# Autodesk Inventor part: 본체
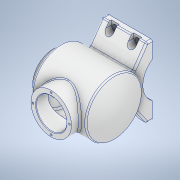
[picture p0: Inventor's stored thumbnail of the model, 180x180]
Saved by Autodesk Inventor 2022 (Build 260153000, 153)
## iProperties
Created: 2023-04
Part Number: 본체
Material: 알루미늄 6061
Document SubType Name: Modeling
Designer: Admin
Density: 2.7 g/cm^3
Appearance: 알루미늄 - 평지
Mass: 1326.81 g
Surface Area: 1066.21 cm^2
Volume: 491.413 cm^3
Author: Admin
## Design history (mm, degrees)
sketch "스케치1" dims "d7" = 226
  geometry: L1 (-211.2, 0)-(105.2, 0) reference; L2 (0, -158.2)-(0, 158.2) reference; L3 (-60, 0)-(-48, 0); L4 (-48, 0)-(-48, 36); L5 (-48, 36)-(-60, 36); L6 (-60, 36)-(-60, 0); L7 (-48, 0)-(60, 0); L8 (60, 0)-(60, 50); L9 (48.336, 50)-(-48, 50); L10 (-48, 50)-(-48, 0); L11 (-34.38, 0)-(50.398, 0); 5 further points
  constraints: 18 end point, 4 parallel, 4 point on line, 2 horizontal, 2 perpendicular, 1 vertical, 4 other
  dimensions: "d0" = 72 diameter of L5 L1; "d1" = 100 diameter of L9 L1; "d3" = 120 distance between parallel lines of L8 L6; "d4" = 108 distance between parallel lines of L8 L4
revolve "회전1" sketch "스케치1" stored, may be unused: angle "d5" = 360 deg
sketch "스케치3" dims "d12" = 226
  geometry: L1 (-60, 0)-(-41, 0); L2 (-41, 0)-(-41, 27); L3 (-41, 27)-(-60, 27); L4 (-60, 27)-(-60, 0); L5 (-41, 0)-(53, 0); L6 (53, 0)-(53, 43); L7 (53, 43)-(-41, 43); L8 (-41, 43)-(-41, 0); L9 (0, -158.2)-(0, 158.2) reference; L10 (-211.2, 0)-(105.2, 0) reference; L11 (48.336, -50)-(48.336, 50) reference; L12 (-60, -36)-(-60, 36) reference; C1 r 106 at (-53, 0); 4 further points
  constraints: 16 end point, 4 parallel, 2 collinear, 2 horizontal, 2 perpendicular, 1 centre point, 1 midpoint, 1 tangent, 3 other
  dimensions: "d8" = 19 distance between parallel lines of L2 L4; "d9" = 54 diameter of L3 L10; "d10" = 86 diameter of L7 L10; "d17" = 7 dimension on C1
revolve "회전2" sketch "스케치3" stored, may be unused: angle "d18" = 90 deg
node "작업 평면1"
sketch "스케치4"
  geometry: L1 (-79.6, 0)-(57.6, 0) reference; L2 (0, -50.4)-(0, 50.4) reference; L3 (-60, -36)-(-60, 36) reference; C1 r 36 at (2, 0); 1 further point
  constraints: 1 centre point, 1 point on line
  dimensions: "d20" = 62 distance from line of C1.centre L3; "d21" = 72 diameter of C1
extrude "돌출1" join sketch "스케치4" stored distance "d22" = 10; taper "d23" = 0 deg
sketch "스케치5"
  geometry: C1 r 36 at (0, 0) reference; C2 r 27 at (0, 0); 1 further point
  constraints: 1 centre point, 1 coincident
  dimensions: "d24" = 54 diameter of C2
extrude "돌출2" cut sketch "스케치5" stored distance "d25" = 10; taper "d26" = 0 deg
sketch "스케치6"
  geometry: L1 (0, -70)-(0, 70) reference; L2 (-70, 0)-(70, 0) reference; A1 r 32.5 centre (0, 0) between (32.5, 0) and (0, -32.5); 3 further points
  constraints: 4 point on circle, 4 point on line, 1 centre point, 1 coincident
  dimensions: "d27" = 65 diameter of A1
hole "구멍1" sketch "스케치6" at (32.5, 0), (0, -32.5), (-32.5, 0), (0, 32.5) diameter "d28" = 3.242; stored, may be unused: countersink angle "d32" = 90 deg, drill point angle "d34" = 118 deg; dims "d29" = 8, "d30" = 4, "d31" = 2, "d33" = 10
sketch "스케치7" dims "d35" = 65
  geometry: L1 (-86, 0)-(82, 0) reference; C1 r 27 at (0, 0) reference; 6 further points
  constraints: 1 coincident, 1 horizontal alignment, 1 point on line, 7 other
  dimensions: "d38" = 360 deg dimension on C1.centre point (-32.5, 0) (derived)
hole "구멍2" sketch "스케치7" at (-32.5, 0), (0, -32.5), (32.5, 0), (0, 32.5) diameter "d40" = 3.242; stored, may be unused: countersink angle "d44" = 90 deg, drill point angle "d46" = 118 deg; dims "d41" = 8, "d42" = 4, "d43" = 2, "d45" = 10
node "작업 평면2"
sketch "스케치8"
  geometry: L1 (0, -70)-(0, 70) reference; L2 (-77, 64.015)-(-77, -74.706); L3 (-77, -62)-(-67, -62); L4 (-67, -62)-(-40.123, -23.615); L5 (-105.4, 0)-(93.4, 0) reference; L6 (-46.557, 0)-(-77, 0); L7 (-77, -62)-(-77, 0); C1 r 43 at (0, 0) reference; A1 r 46.557 centre (0, 0) between (-40.123, -23.615) and (-46.557, 0); 1 further point
  constraints: 10 end point, 4 point on line, 2 point on circle, 1 centre point, 1 coincident, 1 collinear, 1 horizontal, 1 vertical
  dimensions: "d48" = 77 distance between parallel lines of L1 L2; "d49" = 10 distance of L3.start L3.end; "d50" = 55 deg angle of L3 L4; "d51" = 62 distance between parallel lines of L5 L3; "d55" = 93.11303 diameter of A1
extrude "돌출3" join sketch "스케치8" distance "d56" = 80; taper "d57" = 0 deg
sketch "스케치9"
  geometry: L1 (-60, -38.5)-(-108.227, -38.5); L2 (-60, 38.5)-(-108.227, 38.5); L3 (-77, 62)-(-67, 62) reference; L4 (-77, -62)-(-67, -62) reference; L5 (-177.4, 0)-(105.4, 0) reference; L6 (-60, 38.5)-(-60, -38.5); L7 (-77, 62)-(-77, -62) reference; C1 r 38.5 at (-98.5, 0); 3 further points
  constraints: 6 end point, 2 horizontal, 2 tangent, 1 centre point, 1 point on line, 1 vertical, 1 other
  dimensions: "d58" = 77 distance between parallel lines of L2 L1; "d59" = 17 distance between parallel lines of L7 L6
extrude "돌출4" cut sketch "스케치9" stored distance "d61" = 80; taper "d62" = 0 deg
sketch "스케치11"
  geometry: L1 (80, 124)-(0, 124) reference; L2 (80, 0)-(0, 0) reference; L3 (124, 62)-(-44, 62) reference; L4 (107.736, 116)-(-32.889, 116); L5 (107.736, 8)-(-41.889, 8); L6 (60, 143.936)-(60, -34.577); L7 (80, 30.063)-(80, 0) reference; L8 (20, 139.994)-(20, -34.577); 5 further points
  constraints: 8 end point, 8 point on line, 2 horizontal, 2 vertical
  dimensions: "d63" = 108 distance between parallel lines of L4 L5; "d64" = 8 distance between parallel lines of L2 L5; "d65" = 20 distance between parallel lines of L7 L6; "d66" = 40 distance between parallel lines of L6 L8
hole "구멍3" sketch "스케치11" at (60, 8), (20, 8), (60, 116), (20, 116) diameter "d67" = 9; stored, may be unused: countersink angle "d71" = 90 deg, drill point angle "d73" = 0 deg; dims "d68" = 8, "d69" = 4, "d70" = 2, "d72" = 6
sketch "스케치12"
  geometry: L1 (60, 8)-(-20, 8) reference; L2 (7, 8)-(7, -17.501); L3 (-7, 8)-(-7, -18.063); L4 (7, 8)-(-7, 8); C1 r 4.5 at (0, 0) reference; C2 r 7 at (0, 0); 3 further points
  constraints: 6 end point, 2 point on line, 2 tangent, 2 vertical, 1 centre point, 1 coincident
  dimensions: "d74" = 14 diameter of C2
extrude "돌출5" cut sketch "스케치12" distance "d75" = 30; taper "d76" = 0 deg
node "작업 평면5"
sketch "스케치15"
  geometry: L1 (60, 36)-(60, -36) reference; L2 (84, 0)-(-84, 0) reference; 2 further points
  constraints: 1 point on line, 1 other
  dimensions: "d83" = 62 distance from line of L1 point (-2, 0)
feature "엠보싱2" sketch "스케치15" dims "d84" = 0.5, "d85" = 0
fillet "모깎기1" dims "d86" = 3
fillet "모깎기2" dims "d87" = 3
chamfer "모따기1" distance "d88" = 1; stored, may be unused: second distance "d89" = 2, angle "d90" = 45 deg
fillet "모깎기3" dims "d91" = 3
node "솔리드1"
mirror "미러1"
mirror "미러2"
mirror "미러3"
feature "A9D066F2-1C7D-4E18-AEED-F7BC21143FA4" dims "d67" = 9, "d68" = 8, "d69" = 4, "d70" = 2, "d71" = 90 deg, "d72" = 6, "d73" = 0
other parameters: "d19" = 65, "d82" = -185.75
